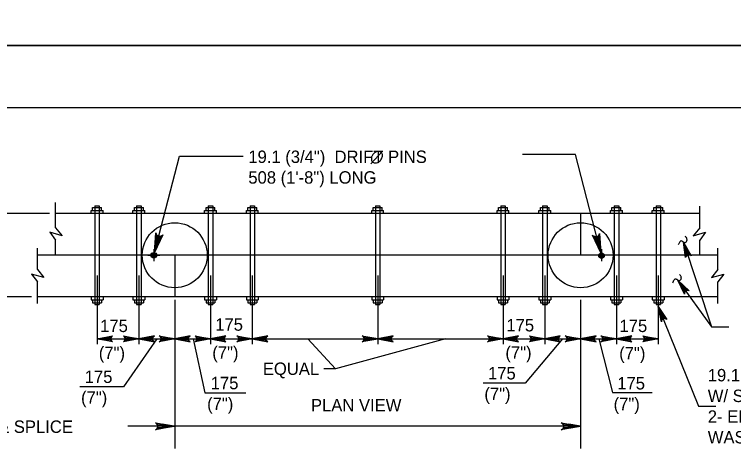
# Model space of a CAD drawing. Extents: x 635440 to 640306, y 296653 to 298484.
# Drawn here: x 639025.5 to 639199.3, y 297743.5 to 297849 of the extents above; entities that cross this region are included whole.
import ezdxf

# ---------------------------------------------------------------- set-up
doc = ezdxf.new("R2010")
doc.units = 0
for name, color, linetype in [('2', 7, 'Continuous'), ('4', 7, 'Continuous'), ('5', 7, 'Continuous'), ('52', 7, 'Continuous'), ('PLT-BNDY', 7, 'Continuous')]:
    doc.layers.add(name, color=color, linetype=linetype)

msp = doc.modelspace()

# ---------------------------------------------------------------- linework, layer by layer
at = {"layer": '2'}
msp.add_line((638475.46, 297826.46), (639261.46, 297826.46), dxfattribs=at)
at = {"layer": '4'}
for p, q in [((639035.46, 297797.39), (639035.46, 297803.49)), ((639044.43, 297801.56), (639044.43, 297802.28)), ((639044.43, 297802.28), (639046.6, 297802.28)), ((639044.97, 297802.64), (639046.05, 297802.64)), ((639044.97, 297802.64), (639044.97, 297778.85)), ((639046.05, 297802.64), (639046.05, 297778.85)), ((639046.6, 297801.56), (639046.6, 297802.28)), ((639054.53, 297801.56), (639054.53, 297802.28)), ((639054.53, 297802.28), (639056.69, 297802.28)), ((639055.07, 297802.64), (639056.15, 297802.64)), ((639055.07, 297802.64), (639055.07, 297778.85)), ((639056.15, 297802.64), (639056.15, 297778.85)), ((639056.69, 297801.56), (639056.69, 297802.28)), ((639071.83, 297801.56), (639071.83, 297802.28)), ((639071.83, 297802.28), (639073.99, 297802.28)), ((639072.37, 297802.64), (639073.45, 297802.64)), ((639072.37, 297802.64), (639072.37, 297778.85)), ((639073.45, 297802.64), (639073.45, 297778.85)), ((639073.99, 297801.56), (639073.99, 297802.28)), ((639081.92, 297802.28), (639084.08, 297802.28)), ((639081.92, 297801.56), (639081.92, 297802.28)), ((639082.46, 297802.64), (639083.54, 297802.64)), ((639082.46, 297802.64), (639082.46, 297778.85)), ((639083.54, 297802.64), (639083.54, 297778.85)), ((639084.08, 297801.56), (639084.08, 297802.28)), ((639112.2, 297801.56), (639112.2, 297802.28)), ((639112.2, 297802.28), (639114.36, 297802.28)), ((639112.74, 297802.64), (639113.82, 297802.64)), ((639112.74, 297802.64), (639112.74, 297778.85)), ((639113.82, 297802.64), (639113.82, 297778.85)), ((639114.36, 297801.56), (639114.36, 297802.28)), ((639142.48, 297802.28), (639144.64, 297802.28)), ((639142.48, 297801.56), (639142.48, 297802.28)), ((639143.02, 297802.64), (639144.1, 297802.64)), ((639143.02, 297802.64), (639143.02, 297778.85)), ((639144.1, 297802.64), (639144.1, 297778.85)), ((639144.64, 297801.56), (639144.64, 297802.28)), ((639152.57, 297801.56), (639152.57, 297802.28)), ((639152.57, 297802.28), (639154.73, 297802.28)), ((639153.11, 297802.64), (639154.19, 297802.64)), ((639153.11, 297802.64), (639153.11, 297778.85)), ((639154.19, 297802.64), (639154.19, 297778.85)), ((639154.73, 297801.56), (639154.73, 297802.28)), ((639169.87, 297801.56), (639169.87, 297802.28)), ((639169.87, 297802.28), (639172.03, 297802.28)), ((639170.41, 297802.64), (639171.5, 297802.64)), ((639170.41, 297802.64), (639170.41, 297778.85)), ((639171.5, 297802.64), (639171.5, 297778.85)), ((639172.03, 297801.56), (639172.03, 297802.28)), ((639179.96, 297801.56), (639179.96, 297802.28)), ((639179.96, 297802.28), (639182.13, 297802.28)), ((639180.51, 297802.64), (639181.59, 297802.64)), ((639180.51, 297802.64), (639180.51, 297778.85)), ((639181.59, 297802.64), (639181.59, 297778.85)), ((639182.13, 297801.56), (639182.13, 297802.28)), ((639191.1, 297797.39), (639191.1, 297802.61)), ((639191.1, 297800.84), (639035.46, 297800.84)), ((639044.07, 297800.84), (639044.07, 297801.56)), ((639044.07, 297801.56), (639046.96, 297801.56)), ((639046.96, 297800.84), (639046.96, 297801.56)), ((639054.16, 297800.84), (639054.16, 297801.56)), ((639054.16, 297801.56), (639057.05, 297801.56)), ((639057.05, 297800.84), (639057.05, 297801.56)), ((639071.47, 297800.84), (639071.47, 297801.56)), ((639071.47, 297801.56), (639074.35, 297801.56)), ((639074.35, 297800.84), (639074.35, 297801.56)), ((639081.56, 297801.56), (639084.44, 297801.56)), ((639081.56, 297800.84), (639081.56, 297801.56)), ((639084.44, 297800.84), (639084.44, 297801.56)), ((639111.84, 297800.84), (639111.84, 297801.56)), ((639111.84, 297801.56), (639114.72, 297801.56)), ((639114.72, 297800.84), (639114.72, 297801.56)), ((639142.12, 297801.56), (639145, 297801.56)), ((639142.12, 297800.84), (639142.12, 297801.56)), ((639145, 297800.84), (639145, 297801.56)), ((639152.21, 297800.84), (639152.21, 297801.56)), ((639152.21, 297801.56), (639155.09, 297801.56)), ((639155.09, 297800.84), (639155.09, 297801.56)), ((639162.3, 297800.84), (639162.3, 297790.74)), ((639169.51, 297800.84), (639169.51, 297801.56)), ((639169.51, 297801.56), (639172.4, 297801.56)), ((639172.4, 297800.84), (639172.4, 297801.56)), ((639179.6, 297800.84), (639179.6, 297801.56)), ((639179.6, 297801.56), (639182.49, 297801.56)), ((639182.49, 297800.84), (639182.49, 297801.56)), ((639035.46, 297797.39), (639037.04, 297795.44)), ((639191.1, 297797.39), (639189.52, 297795.44)), ((639037.04, 297795.44), (639034.06, 297796.29)), ((639034.06, 297796.29), (639035.46, 297794.37)), ((639189.52, 297795.44), (639192.5, 297796.29)), ((639192.5, 297796.29), (639191.1, 297794.37)), ((639035.46, 297790.74), (639035.46, 297794.37)), ((639191.1, 297790.74), (639191.1, 297794.37)), ((639031.09, 297787.3), (639031.09, 297792.43)), ((639059.21, 297792.18), (639059.21, 297789.3)), ((639167.35, 297792.18), (639167.35, 297789.3)), ((639195.46, 297787.3), (639195.46, 297792.43)), ((639195.46, 297790.74), (639031.09, 297790.74)), ((639057.77, 297790.74), (639060.65, 297790.74)), ((639064.26, 297790.74), (639064.26, 297780.65)), ((639168.79, 297790.74), (639165.91, 297790.74)), ((639031.09, 297787.3), (639032.68, 297785.35)), ((639195.46, 297787.3), (639193.88, 297785.35)), ((639029.7, 297786.19), (639031.09, 297784.28)), ((639032.68, 297785.35), (639029.7, 297786.19)), ((639193.88, 297785.35), (639196.86, 297786.19)), ((639196.86, 297786.19), (639195.46, 297784.28)), ((639031.09, 297779.07), (639031.09, 297784.28)), ((639195.46, 297779.07), (639195.46, 297784.28)), ((639195.46, 297780.65), (639031.09, 297780.65)), ((639044.07, 297780.65), (639044.07, 297779.93)), ((639044.07, 297779.93), (639046.96, 297779.93)), ((639044.43, 297779.93), (639044.43, 297779.21)), ((639046.6, 297779.93), (639046.6, 297779.21)), ((639046.96, 297780.65), (639046.96, 297779.93)), ((639054.16, 297780.65), (639054.16, 297779.93)), ((639054.16, 297779.93), (639057.05, 297779.93)), ((639054.53, 297779.93), (639054.53, 297779.21)), ((639056.69, 297779.93), (639056.69, 297779.21)), ((639057.05, 297780.65), (639057.05, 297779.93)), ((639071.47, 297780.65), (639071.47, 297779.93)), ((639071.47, 297779.93), (639074.35, 297779.93)), ((639071.83, 297779.93), (639071.83, 297779.21)), ((639073.99, 297779.93), (639073.99, 297779.21)), ((639074.35, 297780.65), (639074.35, 297779.93)), ((639081.56, 297780.65), (639081.56, 297779.93)), ((639081.56, 297779.93), (639084.44, 297779.93)), ((639081.92, 297779.93), (639081.92, 297779.21)), ((639084.08, 297779.93), (639084.08, 297779.21)), ((639084.44, 297780.65), (639084.44, 297779.93)), ((639111.84, 297780.65), (639111.84, 297779.93)), ((639111.84, 297779.93), (639114.72, 297779.93)), ((639112.2, 297779.93), (639112.2, 297779.21)), ((639114.36, 297779.93), (639114.36, 297779.21)), ((639114.72, 297780.65), (639114.72, 297779.93)), ((639142.12, 297780.65), (639142.12, 297779.93)), ((639142.12, 297779.93), (639145, 297779.93)), ((639142.48, 297779.93), (639142.48, 297779.21)), ((639144.64, 297779.93), (639144.64, 297779.21)), ((639145, 297780.65), (639145, 297779.93)), ((639152.21, 297780.65), (639152.21, 297779.93)), ((639152.21, 297779.93), (639155.09, 297779.93)), ((639152.57, 297779.93), (639152.57, 297779.21)), ((639154.73, 297779.93), (639154.73, 297779.21)), ((639155.09, 297780.65), (639155.09, 297779.93)), ((639169.51, 297780.65), (639169.51, 297779.93)), ((639169.51, 297779.93), (639172.4, 297779.93)), ((639169.87, 297779.93), (639169.87, 297779.21)), ((639172.03, 297779.93), (639172.03, 297779.21)), ((639172.4, 297780.65), (639172.4, 297779.93)), ((639179.6, 297780.65), (639179.6, 297779.93)), ((639179.6, 297779.93), (639182.49, 297779.93)), ((639179.96, 297779.93), (639179.96, 297779.21)), ((639182.13, 297779.93), (639182.13, 297779.21)), ((639182.49, 297780.65), (639182.49, 297779.93)), ((639044.43, 297779.21), (639046.6, 297779.21)), ((639044.97, 297778.85), (639046.05, 297778.85)), ((639054.53, 297779.21), (639056.69, 297779.21)), ((639055.07, 297778.85), (639056.15, 297778.85)), ((639071.83, 297779.21), (639073.99, 297779.21)), ((639072.37, 297778.85), (639073.45, 297778.85)), ((639081.92, 297779.21), (639084.08, 297779.21)), ((639082.46, 297778.85), (639083.54, 297778.85)), ((639112.2, 297779.21), (639114.36, 297779.21)), ((639112.74, 297778.85), (639113.82, 297778.85)), ((639142.48, 297779.21), (639144.64, 297779.21)), ((639143.02, 297778.85), (639144.1, 297778.85)), ((639152.57, 297779.21), (639154.73, 297779.21)), ((639153.11, 297778.85), (639154.19, 297778.85)), ((639169.87, 297779.21), (639172.03, 297779.21)), ((639170.41, 297778.85), (639171.5, 297778.85)), ((639179.96, 297779.21), (639182.13, 297779.21)), ((639180.51, 297778.85), (639181.59, 297778.85))]:
    msp.add_line(p, q, dxfattribs=at)
for centre in [(639064.26, 297790.74), (639162.3, 297790.74)]:
    msp.add_circle(centre, 7.85, dxfattribs=at)
at = {"layer": '5'}
for p, q in [((639111.66, 297812.8), (639114.46, 297815.87)), ((639034.02, 297800.84), (639008.36, 297800.84)), ((639187.15, 297793.93), (639193.93, 297773.44)), ((639045.51, 297785.82), (639045.51, 297769.28)), ((639055.61, 297785.82), (639055.61, 297769.28)), ((639072.91, 297785.82), (639072.91, 297769.28)), ((639083, 297785.82), (639083, 297769.28)), ((639113.28, 297785.82), (639113.28, 297769.28)), ((639143.56, 297785.82), (639143.56, 297769.28)), ((639153.65, 297785.82), (639153.65, 297769.28)), ((639170.95, 297785.82), (639170.95, 297769.28)), ((639181.05, 297785.82), (639181.05, 297769.28)), ((639185.76, 297784.73), (639193.93, 297773.44)), ((639029.65, 297780.65), (639008.36, 297780.65)), ((639064.26, 297779.93), (639064.26, 297744.02)), ((639162.3, 297779.93), (639162.3, 297744.02)), ((639193.93, 297773.44), (639198.1, 297773.44)), ((639045.51, 297770.52), (639113.28, 297770.52)), ((639096.44, 297770.52), (639103.08, 297763.3)), ((639129.7, 297770.52), (639103.08, 297763.3)), ((639113.28, 297770.52), (639181.05, 297770.52)), ((639103.08, 297763.3), (639100.24, 297763.3)), ((639190.8, 297754.25), (639194.97, 297754.25)), ((639162.3, 297749.4), (639052.96, 297749.4))]:
    msp.add_line(p, q, dxfattribs=at)
for points in [[(639059.37, 297791.39), (639065.41, 297814.65), (639080.81, 297814.65)], [(639167.21, 297791.28), (639161.06, 297815.08), (639148.28, 297815.08)], [(639059.37, 297791.39), (639059.7, 297796.12), (639059.78, 297795.91), (639059.85, 297795.71), (639059.98, 297795.58), (639060.11, 297795.45), (639060.25, 297795.39), (639060.4, 297795.32), (639060.55, 297795.31), (639060.71, 297795.3), (639060.89, 297795.35), (639061.06, 297795.4), (639061.23, 297795.54), (639061.39, 297795.68), (639059.37, 297791.39), (639061.23, 297795.54), (639061.06, 297795.4), (639059.37, 297791.39), (639060.89, 297795.35), (639060.71, 297795.3), (639059.37, 297791.39), (639060.55, 297795.31), (639060.4, 297795.32), (639059.37, 297791.39), (639060.25, 297795.39), (639060.11, 297795.45), (639059.37, 297791.39), (639059.98, 297795.58), (639059.85, 297795.71), (639059.37, 297791.39), (639059.78, 297795.91)], [(639167.21, 297791.28), (639165.2, 297795.58), (639165.36, 297795.43), (639165.53, 297795.29), (639165.7, 297795.24), (639165.88, 297795.19), (639166.03, 297795.2), (639166.19, 297795.22), (639166.34, 297795.28), (639166.48, 297795.35), (639166.61, 297795.48), (639166.74, 297795.6), (639166.81, 297795.81), (639166.89, 297796.01), (639167.21, 297791.28), (639166.81, 297795.81), (639166.74, 297795.6), (639167.21, 297791.28), (639166.61, 297795.48), (639166.48, 297795.35), (639167.21, 297791.28), (639166.34, 297795.28), (639166.19, 297795.22), (639167.21, 297791.28), (639166.03, 297795.2), (639165.88, 297795.19), (639167.21, 297791.28), (639165.7, 297795.24), (639165.53, 297795.29), (639167.21, 297791.28), (639165.36, 297795.43)], [(639187.15, 297793.93), (639188.99, 297790.61), (639188.71, 297790.82), (639188.42, 297790.89), (639188.17, 297790.85), (639187.95, 297790.73), (639187.76, 297790.51), (639187.66, 297790.18), (639187.15, 297793.93), (639187.76, 297790.51), (639187.95, 297790.73), (639187.15, 297793.93), (639188.17, 297790.85), (639188.42, 297790.89), (639187.15, 297793.93), (639188.71, 297790.82)], [(639185.76, 297784.73), (639188.51, 297782.12), (639188.19, 297782.23), (639187.9, 297782.21), (639187.67, 297782.09), (639187.49, 297781.91), (639187.37, 297781.65), (639187.38, 297781.3), (639185.76, 297784.73), (639187.37, 297781.65), (639187.49, 297781.91), (639185.76, 297784.73), (639187.67, 297782.09), (639187.9, 297782.21), (639185.76, 297784.73), (639188.19, 297782.23)], [(639181.05, 297778.37), (639190.8, 297754.25)], [(639181.05, 297778.37), (639183.09, 297775.18), (639182.8, 297775.37), (639182.51, 297775.41), (639182.26, 297775.36), (639182.05, 297775.22), (639181.87, 297774.99), (639181.8, 297774.65), (639181.05, 297778.37), (639181.87, 297774.99), (639182.05, 297775.22), (639181.05, 297778.37), (639182.26, 297775.36), (639182.51, 297775.41), (639181.05, 297778.37), (639182.8, 297775.37)], [(639045.51, 297770.52), (639049.24, 297771.22), (639048.96, 297771.02), (639048.81, 297770.77), (639048.76, 297770.52), (639048.81, 297770.27), (639048.96, 297770.02), (639049.24, 297769.82), (639045.51, 297770.52), (639048.96, 297770.02), (639048.81, 297770.27), (639045.51, 297770.52), (639048.76, 297770.52), (639048.81, 297770.77), (639045.51, 297770.52), (639048.96, 297771.02)], [(639055.61, 297770.52), (639051.88, 297769.82), (639052.16, 297770.02), (639052.31, 297770.27), (639052.36, 297770.52), (639052.31, 297770.77), (639052.16, 297771.02), (639051.88, 297771.22), (639055.61, 297770.52), (639052.16, 297771.02), (639052.31, 297770.77), (639055.61, 297770.52), (639052.36, 297770.52), (639052.31, 297770.27), (639055.61, 297770.52), (639052.16, 297770.02)], [(639055.61, 297770.52), (639059.34, 297769.82), (639059.05, 297770.02), (639058.9, 297770.27), (639058.86, 297770.52), (639058.9, 297770.77), (639059.05, 297771.02), (639059.34, 297771.22), (639055.61, 297770.52), (639059.05, 297771.02), (639058.9, 297770.77), (639055.61, 297770.52), (639058.86, 297770.52), (639058.9, 297770.27), (639055.61, 297770.52), (639059.05, 297770.02)], [(639064.26, 297770.52), (639060.53, 297769.82), (639060.81, 297770.02), (639060.96, 297770.27), (639061.01, 297770.52), (639060.96, 297770.77), (639060.81, 297771.02), (639060.53, 297771.22), (639064.26, 297770.52), (639060.81, 297771.02), (639060.96, 297770.77), (639064.26, 297770.52), (639061.01, 297770.52), (639060.96, 297770.27), (639064.26, 297770.52), (639060.81, 297770.02)], [(639064.26, 297770.52), (639067.99, 297769.82), (639067.7, 297770.02), (639067.55, 297770.27), (639067.51, 297770.52), (639067.55, 297770.77), (639067.7, 297771.02), (639067.99, 297771.22), (639064.26, 297770.52), (639067.7, 297771.02), (639067.55, 297770.77), (639064.26, 297770.52), (639067.51, 297770.52), (639067.55, 297770.27), (639064.26, 297770.52), (639067.7, 297770.02)], [(639072.91, 297770.52), (639069.18, 297769.82), (639069.47, 297770.02), (639069.62, 297770.27), (639069.66, 297770.52), (639069.62, 297770.77), (639069.47, 297771.02), (639069.18, 297771.22), (639072.91, 297770.52), (639069.47, 297771.02), (639069.62, 297770.77), (639072.91, 297770.52), (639069.66, 297770.52), (639069.62, 297770.27), (639072.91, 297770.52), (639069.47, 297770.02)], [(639072.91, 297770.52), (639076.64, 297769.82), (639076.35, 297770.02), (639076.2, 297770.27), (639076.16, 297770.52), (639076.2, 297770.77), (639076.35, 297771.02), (639076.64, 297771.22), (639072.91, 297770.52), (639076.35, 297771.02), (639076.2, 297770.77), (639072.91, 297770.52), (639076.16, 297770.52), (639076.2, 297770.27), (639072.91, 297770.52), (639076.35, 297770.02)], [(639083, 297770.52), (639079.27, 297769.82), (639079.56, 297770.02), (639079.71, 297770.27), (639079.75, 297770.52), (639079.71, 297770.77), (639079.56, 297771.02), (639079.27, 297771.22), (639083, 297770.52), (639079.56, 297771.02), (639079.71, 297770.77), (639083, 297770.52), (639079.75, 297770.52), (639079.71, 297770.27), (639083, 297770.52), (639079.56, 297770.02)], [(639083, 297770.52), (639086.73, 297769.82), (639086.44, 297770.02), (639086.3, 297770.27), (639086.25, 297770.52), (639086.3, 297770.77), (639086.44, 297771.02), (639086.73, 297771.22), (639083, 297770.52), (639086.44, 297771.02), (639086.3, 297770.77), (639083, 297770.52), (639086.25, 297770.52), (639086.3, 297770.27), (639083, 297770.52), (639086.44, 297770.02)], [(639113.28, 297770.52), (639109.55, 297769.82), (639109.84, 297770.02), (639109.99, 297770.27), (639110.03, 297770.52), (639109.99, 297770.77), (639109.84, 297771.02), (639109.55, 297771.22), (639113.28, 297770.52), (639109.84, 297771.02), (639109.99, 297770.77), (639113.28, 297770.52), (639110.03, 297770.52), (639109.99, 297770.27), (639113.28, 297770.52), (639109.84, 297770.02)], [(639113.28, 297770.52), (639117.01, 297769.82), (639116.72, 297770.02), (639116.57, 297770.27), (639116.53, 297770.52), (639116.57, 297770.77), (639116.72, 297771.02), (639117.01, 297771.22), (639113.28, 297770.52), (639116.72, 297771.02), (639116.57, 297770.77), (639113.28, 297770.52), (639116.53, 297770.52), (639116.57, 297770.27), (639113.28, 297770.52), (639116.72, 297770.02)], [(639143.56, 297770.52), (639139.83, 297769.82), (639140.12, 297770.02), (639140.26, 297770.27), (639140.31, 297770.52), (639140.26, 297770.77), (639140.12, 297771.02), (639139.83, 297771.22), (639143.56, 297770.52), (639140.12, 297771.02), (639140.26, 297770.77), (639143.56, 297770.52), (639140.31, 297770.52), (639140.26, 297770.27), (639143.56, 297770.52), (639140.12, 297770.02)], [(639143.56, 297770.52), (639147.29, 297769.82), (639147, 297770.02), (639146.85, 297770.27), (639146.81, 297770.52), (639146.85, 297770.77), (639147, 297771.02), (639147.29, 297771.22), (639143.56, 297770.52), (639147, 297771.02), (639146.85, 297770.77), (639143.56, 297770.52), (639146.81, 297770.52), (639146.85, 297770.27), (639143.56, 297770.52), (639147, 297770.02)], [(639153.65, 297770.52), (639149.92, 297769.82), (639150.21, 297770.02), (639150.36, 297770.27), (639150.4, 297770.52), (639150.36, 297770.77), (639150.21, 297771.02), (639149.92, 297771.22), (639153.65, 297770.52), (639150.21, 297771.02), (639150.36, 297770.77), (639153.65, 297770.52), (639150.4, 297770.52), (639150.36, 297770.27), (639153.65, 297770.52), (639150.21, 297770.02)], [(639153.65, 297770.52), (639157.38, 297769.82), (639157.09, 297770.02), (639156.94, 297770.27), (639156.9, 297770.52), (639156.94, 297770.77), (639157.09, 297771.02), (639157.38, 297771.22), (639153.65, 297770.52), (639157.09, 297771.02), (639156.94, 297770.77), (639153.65, 297770.52), (639156.9, 297770.52), (639156.94, 297770.27), (639153.65, 297770.52), (639157.09, 297770.02)], [(639162.3, 297770.52), (639158.57, 297769.82), (639158.86, 297770.02), (639159.01, 297770.27), (639159.05, 297770.52), (639159.01, 297770.77), (639158.86, 297771.02), (639158.57, 297771.22), (639162.3, 297770.52), (639158.86, 297771.02), (639159.01, 297770.77), (639162.3, 297770.52), (639159.05, 297770.52), (639159.01, 297770.27), (639162.3, 297770.52), (639158.86, 297770.02)], [(639162.3, 297770.52), (639166.03, 297769.82), (639165.74, 297770.02), (639165.6, 297770.27), (639165.55, 297770.52), (639165.6, 297770.77), (639165.74, 297771.02), (639166.03, 297771.22), (639162.3, 297770.52), (639165.74, 297771.02), (639165.6, 297770.77), (639162.3, 297770.52), (639165.55, 297770.52), (639165.6, 297770.27), (639162.3, 297770.52), (639165.74, 297770.02)], [(639170.95, 297770.52), (639167.22, 297769.82), (639167.51, 297770.02), (639167.66, 297770.27), (639167.7, 297770.52), (639167.66, 297770.77), (639167.51, 297771.02), (639167.22, 297771.22), (639170.95, 297770.52), (639167.51, 297771.02), (639167.66, 297770.77), (639170.95, 297770.52), (639167.7, 297770.52), (639167.66, 297770.27), (639170.95, 297770.52), (639167.51, 297770.02)], [(639170.95, 297770.52), (639174.68, 297769.82), (639174.4, 297770.02), (639174.25, 297770.27), (639174.2, 297770.52), (639174.25, 297770.77), (639174.4, 297771.02), (639174.68, 297771.22), (639170.95, 297770.52), (639174.4, 297771.02), (639174.25, 297770.77), (639170.95, 297770.52), (639174.2, 297770.52), (639174.25, 297770.27), (639170.95, 297770.52), (639174.4, 297770.02)], [(639181.05, 297770.52), (639177.32, 297769.82), (639177.6, 297770.02), (639177.75, 297770.27), (639177.8, 297770.52), (639177.75, 297770.77), (639177.6, 297771.02), (639177.32, 297771.22), (639181.05, 297770.52), (639177.6, 297771.02), (639177.75, 297770.77), (639181.05, 297770.52), (639177.8, 297770.52), (639177.75, 297770.27), (639181.05, 297770.52), (639177.6, 297770.02)], [(639064.26, 297749.4), (639059.6, 297748.53), (639059.95, 297748.77), (639060.14, 297749.09), (639060.19, 297749.4), (639060.14, 297749.71), (639059.95, 297750.02), (639059.6, 297750.27), (639064.26, 297749.4), (639059.95, 297750.02), (639060.14, 297749.71), (639064.26, 297749.4), (639060.19, 297749.4), (639060.14, 297749.09), (639064.26, 297749.4), (639059.95, 297748.77)], [(639162.3, 297749.4), (639157.64, 297748.53), (639158, 297748.77), (639158.19, 297749.09), (639158.24, 297749.4), (639158.19, 297749.71), (639158, 297750.02), (639157.64, 297750.27), (639162.3, 297749.4), (639158, 297750.02), (639158.19, 297749.71), (639162.3, 297749.4), (639158.24, 297749.4), (639158.19, 297749.09), (639162.3, 297749.4), (639158, 297748.77)]]:
    msp.add_lwpolyline(points, dxfattribs=at)
for points in [[(639181.05, 297778.37), (639181.92, 297775.54), (639182.38, 297775.73)], [(639110.4, 297771), (639110.4, 297770.04), (639113.28, 297770.52)], [(639116.16, 297770.04), (639116.16, 297771), (639113.28, 297770.52)], [(639061.25, 297749.88), (639061.25, 297748.92), (639064.14, 297749.4)], [(639159.42, 297749.88), (639159.42, 297748.92), (639162.3, 297749.4)]]:
    msp.add_lwpolyline(points, close=True, dxfattribs=at)
for centre, radius in [((639059.21, 297790.74), 0.667), ((639059.21, 297790.74), 0.5), ((639059.21, 297790.74), 0.333), ((639059.21, 297790.74), 0.167), ((639167.35, 297790.63), 0.667), ((639167.35, 297790.63), 0.5), ((639167.35, 297790.63), 0.333), ((639167.35, 297790.63), 0.167)]:
    msp.add_circle(centre, radius, dxfattribs=at)
for centre, radius, start, end in [((639187.05, 297794.39), 1.01, 39.8006, 60.652), ((639188.03, 297792.52), 2.27, 153.439, 161.9608), ((639187.81, 297792.63), 2.02, 144.4201, 153.439), ((639189.44, 297791.47), 4.02, 138.3715, 144.4201), ((639186.55, 297794.04), 0.151, 106.7241, 138.3715), ((639186.55, 297794.01), 0.18, 77.4691, 106.7241), ((639186.18, 297792.31), 1.92, 68.5955, 77.4691), ((639186.61, 297793.42), 0.729, 48.0647, 68.5955), ((639187.47, 297794.38), 0.556, 228.0647, 251.6054), ((639187.44, 297794.29), 0.461, 251.6054, 287.1056), ((639187.41, 297794.39), 0.568, 287.1056, 318.9992), ((639187.31, 297794.6), 0.677, 14.2351, 39.8006), ((639187.22, 297794.55), 0.816, 318.9992, 333.439), ((639187.44, 297794.44), 0.571, 333.439, 350.7201), ((639186.21, 297794.32), 1.81, 5.7096, 14.2351), ((639187.43, 297794.45), 0.587, 350.7201, 5.7096), ((639188.05, 297782.26), 4.02, 138.3715, 144.4201), ((639185.16, 297784.83), 0.151, 106.7241, 138.3715), ((639185.16, 297784.8), 0.18, 77.4691, 106.7241), ((639184.79, 297783.1), 1.92, 68.5955, 77.4691), ((639185.22, 297784.22), 0.729, 48.0647, 68.5955), ((639186.08, 297785.17), 0.556, 228.0647, 251.6054), ((639185.66, 297785.18), 1.01, 39.8006, 60.652), ((639186.02, 297785.18), 0.568, 287.1056, 318.9992), ((639185.92, 297785.4), 0.677, 14.2351, 39.8006), ((639185.83, 297785.35), 0.816, 318.9992, 333.439), ((639186.05, 297785.24), 0.571, 333.439, 350.7201), ((639184.82, 297785.12), 1.81, 5.7096, 14.2351), ((639186.04, 297785.24), 0.587, 350.7201, 5.7096), ((639186.64, 297783.32), 2.27, 153.439, 161.9608), ((639186.42, 297783.42), 2.02, 144.4201, 153.439), ((639186.05, 297785.08), 0.461, 251.6054, 287.1056)]:
    msp.add_arc(centre, radius, start, end, dxfattribs=at)
msp.add_spline([(639114.17, 297815.56), (639113.95, 297815.73), (639113.73, 297815.79), (639113.46, 297815.82), (639113.3, 297815.82), (639113.03, 297815.76), (639112.79, 297815.64), (639112.61, 297815.55), (639112.28, 297815.28), (639112.02, 297814.94), (639111.87, 297814.63), (639111.78, 297814.34), (639111.75, 297814.07), (639111.78, 297813.84), (639111.89, 297813.51), (639112.01, 297813.34), (639112.25, 297813.16), (639112.61, 297813.07), (639113.02, 297813.08), (639113.54, 297813.32), (639113.93, 297813.65), (639114.21, 297814.04), (639114.4, 297814.46), (639114.46, 297814.92), (639114.38, 297815.22), (639114.18, 297815.56)], degree=3, dxfattribs=at)
at = {"layer": '52'}
for points in [[(639059.92, 297770.52), (639051.88, 297758.91), (639041.38, 297758.91)], [(639068.68, 297770.52), (639071.5, 297757.47), (639081.4, 297757.47)], [(639157.89, 297770.52), (639148.92, 297759.85), (639138.79, 297759.85)], [(639166.72, 297770.52), (639170.03, 297757.55), (639179.57, 297757.55)]]:
    msp.add_lwpolyline(points, dxfattribs=at)
at = {"layer": 'PLT-BNDY'}
for points in [[(638435.46, 298435.46), (639276.46, 298435.46), (639276.46, 297841.46), (638435.46, 297841.46)], [(638435.46, 297841.46), (639276.46, 297841.46), (639276.46, 297247.46), (638435.46, 297247.46)]]:
    msp.add_lwpolyline(points, close=True, dxfattribs=at)

# ---------------------------------------------------------------- texts
at = {"layer": '5'}
for s, height, p in [('19.1 (3/4")  DRIFT PINS', 3.0001, (639082.04, 297813.04)), ('508 (1\'-8") LONG', 3.0001, (639082.04, 297808.04)), ('175', 3, (639046.25, 297772.17)), ('175', 3, (639074.05, 297772.49)), ('175', 3, (639144.37, 297772.33)), ('175', 3, (639171.69, 297772.17)), ('(7")', 3, (639045.93, 297765.65)), ('(7")', 3, (639073.34, 297765.73)), ('(7")', 3, (639144.13, 297765.73)), ('(7")', 3, (639171.62, 297765.57)), ('EQUAL', 3, (639085.54, 297761.81)), ('175', 3, (639042.52, 297759.86)), ('175', 3, (639139.93, 297760.72)), ('19.1 (3/4")  BOLT', 3.0001, (639193.01, 297760.25)), ('175', 3, (639072.96, 297758.35)), ('175', 3, (639171.15, 297758.29)), ('(7")', 3, (639139.05, 297755.72)), ('(7")', 3, (639041.64, 297754.86)), ('W/ STD. NUT AND', 3.0001, (639193.01, 297755.25)), ('(7")', 3, (639072.09, 297753.35)), ('PLAN VIEW', 3, (639097.17, 297752.99)), ('(7")', 3, (639170.27, 297753.29)), ('2- ENLARGED', 3.0001, (639193.01, 297750.25)), ('L PILE & SPLICE', 3.0001, (639008.45, 297747.8)), ('WASHERS (TYP.)', 3.0001, (639193.01, 297745.25))]:
    msp.add_text(s, height=height, dxfattribs=at).set_placement(p)

doc.saveas('drawing.dxf')
